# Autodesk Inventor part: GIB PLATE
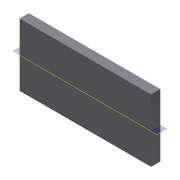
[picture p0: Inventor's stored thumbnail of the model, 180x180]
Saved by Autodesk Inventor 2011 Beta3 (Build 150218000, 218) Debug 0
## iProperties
Shininess: 64.0
Length Units: 11272
Angle Units: 11279
Time Units: 11290
Mass Units: 11286
Length Display Precision: 3
Angle Display Precision: 2
Compacted: True
Part Number: GIB PLATE
Document SubType Name: Modeling
Created: 2003-11
Designer: Autodesk, Inc.
Manufacturer: Standard
Standards Organization: Custom
Mass: 9.82621 g
Surface Area: 12.9097 cm^2
Volume: 1.25015 cm^3
Density: 7.86 g/cm^3
Material: Steel, Mild
Density: 0.0
Volumn: 0.0
Area: 0.0
PropertySet Name: Model Information
Control State: 0
Master: False
Checked Out: False
Author: Autodesk, Inc.
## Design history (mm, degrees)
sketch "Sketch1"
  geometry: L1 (0, 0)-(33.338, 0); L2 (33.338, 0)-(33.338, 15.875); L3 (33.338, 15.875)-(0, 15.875); L4 (0, 15.875)-(0, 0)
  constraints: 8 end point, 2 parallel, 1 horizontal, 1 perpendicular
  dimensions: "d0" = 33.3375 distance of L1.start L1.end; "d1" = 15.875 distance between parallel lines of L1 L3
extrude "Extrusion1" new body sketch "Sketch1" distance "d2" = 2.3622; taper "d3" = 0 deg
workplane "Work Plane1"
body "Solid1"
